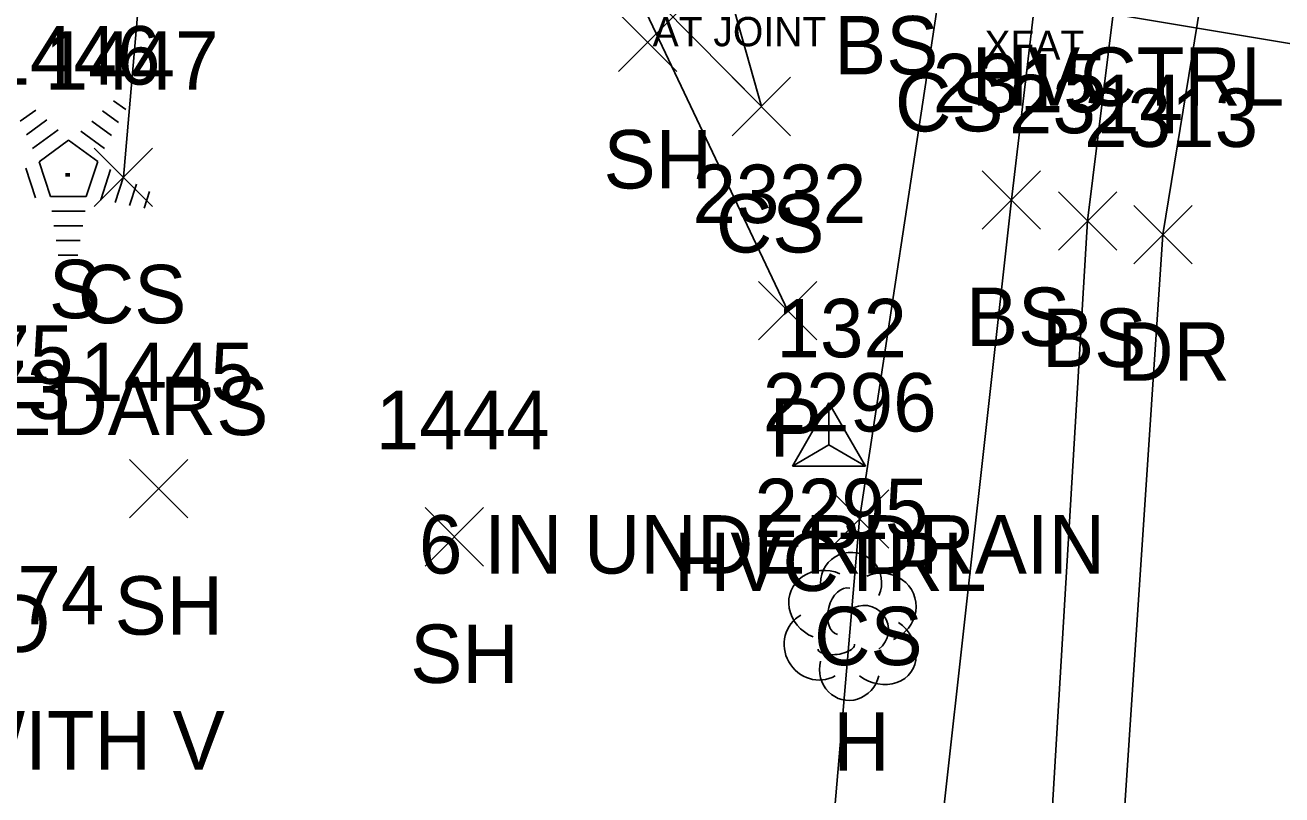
# Model space of a CAD drawing. Extents: x 1761340 to 1763889, y 696770 to 706023.
# Drawn here: x 1761614.72 to 1761657.73, y 700807.03 to 700833.39 of the extents above; entities that cross this region are included whole.
import ezdxf

# ---------------------------------------------------------------- set-up
doc = ezdxf.new("R2010")
doc.units = 0
for name, color, linetype in [('B_A', 7, 'Continuous'), ('B_C', 7, 'Continuous'), ('BF', 7, 'Continuous'), ('C_A', 7, 'Continuous'), ('C_I', 7, 'Continuous'), ('CPSM', 7, 'Continuous'), ('D_A', 7, 'Continuous'), ('D_C', 7, 'Continuous'), ('D_I', 7, 'Continuous'), ('D_TIC', 7, 'Continuous'), ('DCP', 7, 'Continuous'), ('L_A', 7, 'Continuous'), ('L_C', 7, 'Continuous'), ('L_I', 7, 'Continuous'), ('L_TIC', 7, 'Continuous'), ('LELB', 7, 'Continuous'), ('LTC', 7, 'Continuous'), ('LTD', 7, 'Continuous'), ('M_A', 7, 'Continuous'), ('M_C', 7, 'Continuous'), ('M_I', 7, 'Continuous'), ('R_A', 7, 'Continuous'), ('R_I', 7, 'Continuous'), ('R_TIC', 7, 'Continuous'), ('RDP', 7, 'Continuous')]:
    doc.layers.add(name, color=color, linetype=linetype)

msp = doc.modelspace()

# ---------------------------------------------------------------- linework, layer by layer
at = {"layer": 'BF'}
msp.add_lwpolyline([(1761724.868, 700826.95), (1761706.242, 700827.778), (1761692.328, 700828.536), (1761682.079, 700829.49), (1761665.583, 700831.495), (1761649.292, 700834.2), (1761639.519, 700836.163), (1761621.811, 700840.338), (1761606.756, 700844.682), (1761598.241, 700847.438)], dxfattribs=at)
at = {"layer": 'CPSM'}
for p, q in [((1761640.977, 700818.292), (1761642.227, 700820.458)), ((1761643.477, 700818.292), (1761642.227, 700820.458)), ((1761642.228, 700819.014), (1761642.227, 700820.458)), ((1761640.977, 700818.292), (1761642.228, 700819.014)), ((1761642.228, 700819.014), (1761642.228, 700819.014)), ((1761642.228, 700819.014), (1761643.477, 700818.292)), ((1761640.977, 700818.292), (1761643.477, 700818.292))]:
    msp.add_line(p, q, dxfattribs=at)
at = {"layer": 'D_TIC'}
for points in [[(1761639.818, 700822.61), (1761641.818, 700824.61)], [(1761641.818, 700822.61), (1761639.818, 700824.61)]]:
    msp.add_lwpolyline(points, dxfattribs=at)
at = {"layer": 'DCP'}
msp.add_lwpolyline([(1761640.818, 700823.61), (1761622.01, 700863.245)], dxfattribs=at)
at = {"layer": 'L_TIC'}
for points in [[(1761635.024, 700831.793), (1761637.024, 700833.793)], [(1761637.024, 700831.793), (1761635.024, 700833.793)], [(1761638.915, 700829.601), (1761640.915, 700831.601)], [(1761640.915, 700829.601), (1761638.915, 700831.601)], [(1761638.915, 700829.601), (1761640.915, 700831.601)], [(1761640.915, 700829.601), (1761638.915, 700831.601)], [(1761617.082, 700827.178), (1761619.082, 700829.178)], [(1761619.082, 700827.178), (1761617.082, 700829.178)], [(1761647.472, 700826.402), (1761649.472, 700828.402)], [(1761649.472, 700826.402), (1761647.472, 700828.402)], [(1761650.08, 700825.684), (1761652.08, 700827.684)], [(1761652.08, 700825.684), (1761650.08, 700827.684)], [(1761618.294, 700816.519), (1761620.294, 700818.519)], [(1761620.294, 700816.519), (1761618.294, 700818.519)], [(1761642.277, 700815.475), (1761644.277, 700817.475)], [(1761644.277, 700815.475), (1761642.277, 700817.475)], [(1761628.41, 700814.867), (1761630.41, 700816.867)], [(1761630.41, 700814.867), (1761628.41, 700816.867)]]:
    msp.add_lwpolyline(points, dxfattribs=at)
at = {"layer": 'LELB'}
for points in [[(1761650.668, 700568.581), (1761653.72, 700589.345), (1761656.228, 700611.846), (1761650.783, 700645.878), (1761646.693, 700682.268), (1761643.965, 700721.139), (1761646.185, 700763.151), (1761649.001, 700791.974), (1761651.08, 700826.684), (1761655.56, 700862.863), (1761665.437, 700900.351), (1761673.527, 700937.717), (1761682.384, 700964.347), (1761693.002, 701008.082), (1761690.127, 701015.338), (1761683.006, 701019.111)], [(1761647.361, 700568.693), (1761651.507, 700589.637), (1761652.179, 700611.172), (1761648.147, 700645.92), (1761644.284, 700683.035), (1761641.556, 700721.375), (1761643.749, 700763.66), (1761644.587, 700792.445), (1761648.472, 700827.402), (1761652.737, 700863.508), (1761659.58, 700901.674), (1761670.104, 700938.531), (1761679.505, 700964.488), (1761691.194, 701008.19), (1761682.174, 701016.504)], [(1761650.212, 700590.246), (1761648.805, 700610.457), (1761644.582, 700645.542), (1761640.712, 700682.502), (1761639.82, 700689.73), (1761639.14, 700693.979), (1761637.85, 700721.718), (1761639.717, 700763.338), (1761641.24, 700792.73), (1761643.277, 700816.475), (1761646.043, 700834.747), (1761651.107, 700867.028), (1761649.907, 700870.225), (1761650.052, 700873.461)], [(1761639.915, 700830.601), (1761631.782, 700838.831), (1761628.56, 700843.668), (1761624.344, 700853.144), (1761608.772, 700864.631), (1761621.099, 700862.527), (1761628.557, 700864.432)], [(1761618.082, 700828.178), (1761620.121, 700851.662)], [(1761639.915, 700830.601), (1761637.677, 700838.577), (1761638.669, 700843.229)]]:
    msp.add_lwpolyline(points, dxfattribs=at)
at = {"layer": 'LTC'}
for p, q in [((1761617.743, 700830.799), (1761618.162, 700830.495)), ((1761614.554, 700830.094), (1761615.083, 700830.478)), ((1761617.372, 700830.451), (1761617.921, 700830.052)), ((1761614.764, 700829.628), (1761615.467, 700830.139)), ((1761617.001, 700830.103), (1761617.68, 700829.609)), ((1761614.973, 700829.162), (1761615.852, 700829.8)), ((1761615.198, 700828.707), (1761616.209, 700829.442)), ((1761616.209, 700829.442), (1761617.207, 700828.717)), ((1761616.629, 700829.754), (1761617.439, 700829.166)), ((1761615.198, 700828.707), (1761615.585, 700827.514)), ((1761617.207, 700828.717), (1761616.815, 700827.514)), ((1761614.743, 700828.488), (1761615.074, 700827.469)), ((1761617.644, 700828.446), (1761617.306, 700827.406)), ((1761618.089, 700828.195), (1761617.801, 700827.311)), ((1761618.533, 700827.945), (1761618.296, 700827.216)), ((1761616.815, 700827.514), (1761615.585, 700827.514)), ((1761618.977, 700827.695), (1761618.791, 700827.121)), ((1761616.777, 700827.014), (1761615.632, 700827.014)), ((1761616.693, 700826.514), (1761615.705, 700826.514)), ((1761616.609, 700826.014), (1761615.778, 700826.014)), ((1761616.526, 700825.514), (1761615.851, 700825.514))]:
    msp.add_line(p, q, dxfattribs=at)
at = {"layer": 'LTD'}
msp.add_line((1761642.938, 700812.858), (1761642.938, 700812.858), dxfattribs=at)
msp.add_line((1761642.938, 700812.858), (1761642.938, 700812.858), dxfattribs=at)
msp.add_arc((1761642.984, 700814.292), 1.047, 335.5272, 180.9563, dxfattribs=at)
for centre, major_axis, ratio, start_param, end_param in [((1761642.146, 700813.524), (1.21, -0.512), 0.895232, 1.570796, 4.712389), ((1761643.979, 700813.441), (-1.141, -0.483), 0.949671, 1.570796, 4.712389), ((1761642.729, 700813.316), (-0.208, -0.792), 0.645439, 3.141593, 6.283185), ((1761643.438, 700812.691), (-0.5, 0.667), 0.989748, 3.141593, 6.283185), ((1761641.854, 700812.149), (0.584, -1.042), 0.959034, 3.141593, 6.283185), ((1761643.938, 700812.024), (-1.09, 0.792), 0.841452, 1.570796, 4.712389), ((1761642.479, 700812.108), (-0.625, -0.083), 0.423636, 0, 3.141593), ((1761642.938, 700811.358), (0.265, 1.061), 0.942809, 1.570796, 4.712389)]:
    msp.add_ellipse(centre, major_axis=major_axis, ratio=ratio, start_param=start_param, end_param=end_param, dxfattribs=at)
at = {"layer": 'R_TIC'}
for points in [[(1761652.655, 700825.216), (1761654.655, 700827.216)], [(1761654.655, 700825.216), (1761652.655, 700827.216)]]:
    msp.add_lwpolyline(points, dxfattribs=at)
at = {"layer": 'RDP'}
msp.add_lwpolyline([(1761671.259, 700538.434), (1761661.644, 700574.622), (1761657.605, 700611.792), (1761653.176, 700645.742), (1761649.934, 700682.027), (1761646.901, 700721.235), (1761649.099, 700763.058), (1761651.354, 700791.608), (1761653.655, 700826.216), (1761659.48, 700861.884), (1761668.314, 700899.372), (1761676.768, 700936.595), (1761684.872, 700963.935), (1761695.512, 701007.432), (1761695.754, 701009.139), (1761702.957, 701038.717), (1761714.691, 701083.389), (1761730.248, 701133.725)], dxfattribs=at)

# ---------------------------------------------------------------- texts
at = {"layer": 'B_A'}
msp.add_text('XFAT', height=1, dxfattribs=at).set_placement((1761647.548, 700832.2))
at = {"layer": 'B_C'}
msp.add_text('AT JOINT', height=1, dxfattribs=at).set_placement((1761636.192, 700832.663))
at = {"layer": 'C_A'}
for p in [(1761647.109, 700830.623), (1761636.921, 700814.014)]:
    msp.add_text('HVCTRL', height=2, dxfattribs=at).set_placement(p)
at = {"layer": 'C_I'}
msp.add_text('132', height=2, dxfattribs=at).set_placement((1761640.433, 700822.014))
at = {"layer": 'D_A'}
msp.add_text('P', height=2, dxfattribs=at).set_placement((1761640.196, 700818.61))
at = {"layer": 'D_C'}
msp.add_text('6 IN UNDERDRAIN', height=2, dxfattribs=at).set_placement((1761628.196, 700814.61))
at = {"layer": 'D_I'}
msp.add_text('2332', height=2, dxfattribs=at).set_placement((1761637.558, 700826.61))
at = {"layer": 'L_A'}
for s, p in [('BS', (1761642.404, 700831.697)), ('CS', (1761644.484, 700829.747)), ('SH', (1761634.513, 700827.793)), ('CS', (1761638.356, 700825.601)), ('CS', (1761638.356, 700825.601)), ('S', (1761615.535, 700823.351)), ('CS', (1761616.523, 700823.178)), ('BS', (1761646.913, 700822.402)), ('BS', (1761649.52, 700821.684)), ('SH', (1761617.782, 700812.519)), ('CS', (1761641.718, 700811.475)), ('SH', (1761627.898, 700810.867)), ('H', (1761642.371, 700807.858))]:
    msp.add_text(s, height=2, dxfattribs=at).set_placement(p)
at = {"layer": 'L_C'}
msp.add_text('3 S CEDARS', height=2, dxfattribs=at).set_placement((1761607.142, 700819.351))
at = {"layer": 'L_I'}
for s, p in [('1446', (1761613.401, 700831.351)), ('1447', (1761615.39, 700831.178)), ('2315', (1761645.78, 700830.402)), ('2314', (1761648.387, 700829.684)), ('1175', (1761610.425, 700821.108)), ('1445', (1761616.601, 700820.519)), ('2296', (1761639.962, 700819.475)), ('1444', (1761626.717, 700818.867)), ('2295', (1761639.678, 700815.858)), ('1174', (1761611.479, 700812.874))]:
    msp.add_text(s, height=2, dxfattribs=at).set_placement(p)
at = {"layer": 'LTC'}
msp.add_text('.', height=1.037, rotation=270, dxfattribs=at).set_placement((1761616.092, 700828.455))
at = {"layer": 'M_A'}
msp.add_text('BND', height=2, dxfattribs=at).set_placement((1761609.936, 700811.902))
at = {"layer": 'M_C'}
msp.add_text('6X6 UP 6" WITH V', height=2, dxfattribs=at).set_placement((1761599.054, 700807.902))
at = {"layer": 'M_I'}
msp.add_text('1173', height=2, dxfattribs=at).set_placement((1761610.322, 700819.902))
at = {"layer": 'R_A'}
msp.add_text('DR', height=2, dxfattribs=at).set_placement((1761652.089, 700821.216))
at = {"layer": 'R_I'}
msp.add_text('2313', height=2, dxfattribs=at).set_placement((1761650.963, 700829.216))

doc.saveas('drawing.dxf')
